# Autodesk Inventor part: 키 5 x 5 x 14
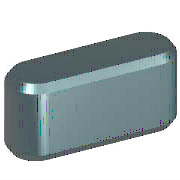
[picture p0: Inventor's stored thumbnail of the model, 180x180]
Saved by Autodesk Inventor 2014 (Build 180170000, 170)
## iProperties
Created: 2012-02
Part Number: 키 5 x 5 x 14
Material: 강철, 연강
Description: 키 및 해당 키홈
Document SubType Name: Modeling
Standard: KS B 1311
Designer: mduedu
Standards Organization: KS
Language: ko-KR
Size Designation: 5 x 5 x 14
Categories: <MemberInstance><Categories><Category DisplayName="샤프트 부품" InternalName="7f7aeb1f-a693-4053-b835-cee3144e0d98" Mnemonic="SHFT"><Category DisplayName="키" Interna
Density: 1 g/cm^3
Appearance: 노란색
IsCustomPart: 1
Author: mduedu
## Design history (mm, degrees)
workplane "Work Plane1"
workplane "Work Plane2"
sketch "스케치1"
  geometry: L1 (2.5, 2.5)-(11.5, 2.5); L2 (11.5, -2.5)-(2.5, -2.5); L3 (0, 9.4)-(0, -7.4) reference; L4 (-5, 0)-(30, 0) reference; L5 (14, 0)-(14, 7); A1 r 2.5 centre (2.5, 0) between (2.5, 2.5) and (2.5, -2.5); A2 r 2.5 centre (11.5, 0) between (11.5, -2.5) and (11.5, 2.5)
  constraints: 6 end point, 5 point on circle, 4 tangent, 3 point on line, 2 centre point, 1 horizontal, 1 parallel, 1 perpendicular
  dimensions: "d0" = 2.5 radius of A1 (= 0.5 x PB); "d13" = 2.5 radius of A2 (= 0.5 x PB); "d14" = 14 distance between parallel lines of L5 L3 (= NLG)
extrude "본체1" new body sketch "스케치1" taper "d3" = 0 deg; stored distance "d4" = 10
workplane "Work Plane3"
body "Solid1"
chamfer "모따기1" distance "d8" = 0.4 (= PHH); stored, may be unused: second distance "d9" = 0.4 (= PHH), angle "d15" = 45 deg
other parameters: "d1" = -3 (= -PNT), "d2" = 2 (= PH - PNT), "NLG" = 14 [user parameter; used in 3 equation terms], "PB" = 5 [user parameter; used in 2 equation terms], "PNT" = 3 [user parameter; used in 2 equation terms], "PH" = 5 [user parameter; used in 1 equation term], "PHH" = 0.4 [user parameter; used in 2 equation terms], "d10" = 0, "d16" = 0, "d17" = 0, "d18" = 0, "WDMIN" = 12 [user parameter], "PLB2" = 14 (= NLG) [user parameter], "WDMAX" = 17 [user parameter], "PLB1" = 14 (= NLG) [user parameter], "RR" = 0.16 [user parameter], "PUEB" = 2.3 [user parameter]
